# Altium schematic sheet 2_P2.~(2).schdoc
size A3; Symbol: Sheet-Symbol_A4; Device: Sheet-Symbol_A4; Company: 嘉立创EDA; Version: V1.0; Page Size: A4; @Project Name: 基于STM32的四旋翼无人机控制系统设计; @Page Count: 2; @Update Date: 2025-06-02; @Create Date: 2025-04-05; @Schematic Name: 基于STM32的无人机控制系统设计_AK09915; @Page No: 2; @Page Name: P2; @Board Name: 基于STM32的无人机控制系统设计_AK09915; @Create Time: 23:31:03; @Update Time: 17:55:10; Width: 1170; Height: 825; Region Start: 1; X Region Count: 6; Y Region Count: 4; Blade Width: 10; Title Block Position: 3
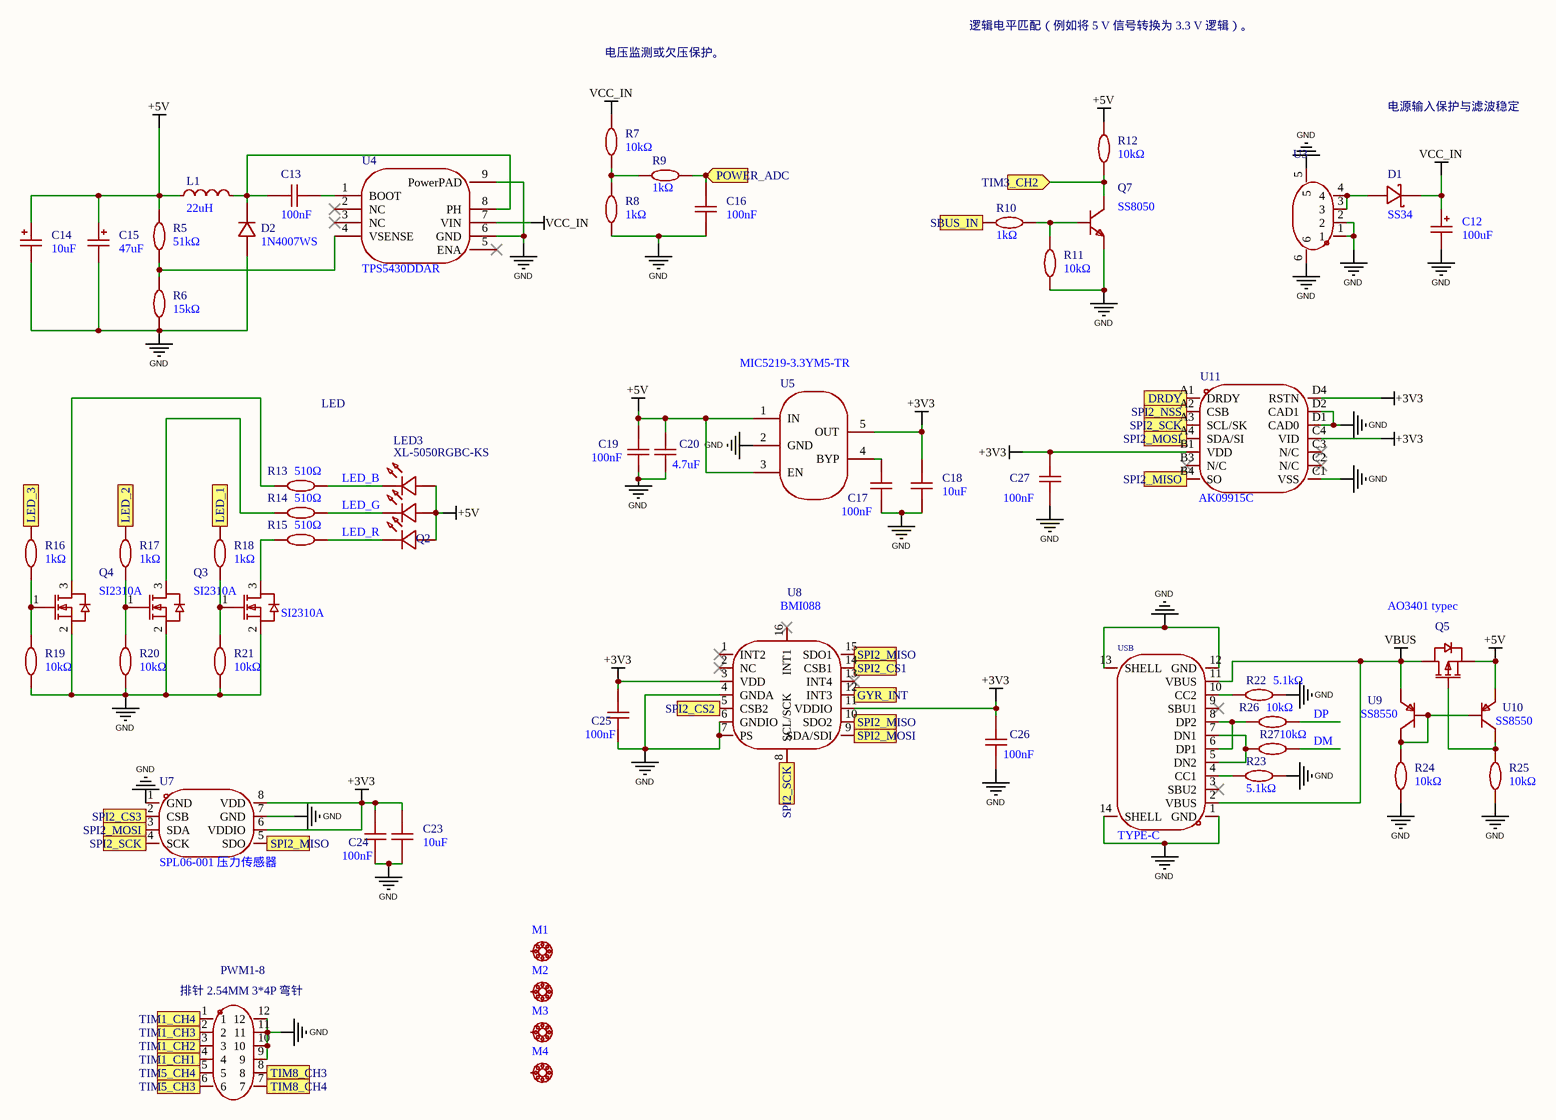
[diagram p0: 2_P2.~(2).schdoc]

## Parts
C12  100uF  [CAP-SMD_L6.0-W3.2-R-RD]
C13  100nF  [C0603]
C14  10uF  [CAP-SMD_L3.2-W1.6-RD-C7171]
C15  47uF  [CASE-A_3216]
C16  100nF  [C0603]
C17  100nF  [C0603]
C18  10uF  [C0603]
C19  100nF  [C0603]
C20  4.7uF  [C0603]
C23  10uF  [C0603]
C24  100nF  [C0603]
C25  100nF  [C0603]
C26  100nF  [C0603]
C27  100nF  [C0603]
D1  SS34  [SMA_L4.3-W2.6-LS5.2-RD]
D2  1N4007WS  [SOD-323_L1.8-W1.3-LS2.5-RD]
L1  22uH  [IND-SMD_L7.3-W6.6_MHCI06030]
LED3  XL-5050RGBC-KS  [LED-ARRAY-SMD_6P-L5.0-W5.0-TL-RD]
M1  M3螺丝  [m3_bd6.2]  (value not drawn)
M2  M3螺丝  [m3_bd6.2]  (value not drawn)
M3  M3螺丝  [m3_bd6.2]  (value not drawn)
M4  M3螺丝  [m3_bd6.2]  (value not drawn)
PWM1-8  排针 2.54MM 3*4P 弯针  [HDR-TH_12P-P2.54-H-M-R3-C4-S2.54-N]
Q2  SI2310A  [SOT-23-3_L2.9-W1.3-P0.95-LS2.4-BR]
Q3  SI2310A  [SOT-23-3_L2.9-W1.3-P0.95-LS2.4-BR]
Q4  SI2310A  [SOT-23-3_L2.9-W1.3-P0.95-LS2.4-BR]
Q5  AO3401 typec  [SOT-23-3_L2.9-W1.4-P1.90-LS2.6-BR]
Q7  SS8050  [SOT-23-3_L2.9-W1.3-P1.90-LS2.4-BR]
R5  51kΩ  [R0603]
R6  15kΩ  [R0603]
R7  10kΩ  [R0603]
R8  1kΩ  [R0603]
R9  1kΩ  [R0603]
R10  1kΩ  [R0603]
R11  10kΩ  [R0603]
R12  10kΩ  [R0603]
R13  510Ω  [R0603]
R14  510Ω  [R0603]
R15  510Ω  [R0603]
R16  1kΩ  [R0603]
R17  1kΩ  [R0603]
R18  1kΩ  [R0603]
R19  10kΩ  [R0603]
R20  10kΩ  [R0603]
R21  10kΩ  [R0603]
R22  5.1kΩ  [R0603]
R23  5.1kΩ  [R0603]
R24  10kΩ  [R0603]
R25  10kΩ  [R0603]
R26  10kΩ  [R0603]
R27  10kΩ  [R0603]
U3  ZX-SH1.0-4PWT  [CONN-SMD_4P-P1.00_MEGASTAR_ZX-SH1.0-4PWT]  (value not drawn)
U4  TPS5430DDAR  [ESOP-8_L4.9-W3.9-P1.27-LS6.0-TL-EP]
U5  MIC5219-3.3YM5-TR  [SOT-23-5_L3.0-W1.7-P0.95-LS2.8-TL]
U7  SPL06-001 压力传感器  [SENSOR-SMD_SPL06-001]
U8  BMI088  [LGA-16_L4.5-W3.0-P0.50-BL]
U9  SS8550  [SOT-23-3_L2.9-W1.3-P1.90-LS2.4-BR]
U10  SS8550  [SOT-23-3_L2.9-W1.3-P1.90-LS2.4-BR]
U11  AK09915C  [BGA-14_L1.6-W1.6-BR-AK09915C]
USB  TYPE-C  [USB-C-SMD_TYPE-C-6PIN-2MD-073]

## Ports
DRDY (in), GYR_INT (in), LED_1 (in), LED_2 (in), LED_3 (in), POWER_ADC (in), SBUS_IN (in), SPI2_CS1 (in), SPI2_CS2 (in), SPI2_CS3 (in), SPI2_MISO (in), SPI2_MOSI (in), SPI2_NSS (in), SPI2_SCK (in), TIM1_CH1 (in), TIM1_CH2 (in), TIM1_CH3 (in), TIM1_CH4 (in), TIM3_CH2 (in), TIM5_CH3 (in), TIM5_CH4 (in), TIM8_CH3 (in), TIM8_CH4 (in)

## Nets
+3V3: C18.2 C23.2 C24.1 C25.1 C26.1 C27.1 U5.5(OUT) U7.6(VDDIO) U7.8(VDD) U8.3(VDD) U8.11(VDDIO) U11.B1(VDD) U11.C4(VID) U11.D4(RSTN)
+5V: C14.1 C15.1 C19.1 C20.2 L1.1 LED3.4 LED3.5 LED3.6 Q5.2(S) R5.2 R12.1 U5.1(IN) U5.3(EN) U10.2(E)
GND: C12.2 C14.2 C15.2 C16.2 C17.2 C18.1 C19.2 C20.1 C23.1 C24.2 C25.2 C26.2 C27.2 D2.2(A) PWM1-8.9 PWM1-8.10 PWM1-8.11 PWM1-8.12 Q2.2(S) Q3.2(S) Q4.2(S) Q7.2(E) R6.1 R8.1 R11.2 R19.1 R20.1 R21.1 R22.2 R23.2 R24.1 R25.1 U3.1 U3.2 U3.5 U3.6 U4.6(GND) U4.9(PowerPAD) U5.2(GND) U7.1(GND) U7.7(GND) U8.4(GNDA) U8.6(GNDIO) U8.7(PS) U11.C1(VSS) U11.D1(CAD0) U11.D2(CAD1) USB.1(GND) USB.12(GND) USB.13(SHELL) USB.14(SHELL)
VBUS: Q5.3(D) U9.2(E) USB.2(VBUS) USB.11(VBUS)
VCC_IN: C12.1 D1.1(K) R7.2 U4.7(VIN)
DM: R27.2
DP: R26.2
DRDY: U11.A1(DRDY) ; port DRDY
GYR_INT: U8.12(INT3) ; port GYR_INT
LED_1: R18.1 ; port LED_1
LED_2: R17.1 ; port LED_2
LED_3: R16.1 ; port LED_3
LED_B: LED3.1 R13.2
LED_G: LED3.2 R14.2
LED_R: LED3.3 R15.2
POWER_ADC: C16.1 R9.1 ; port POWER_ADC
SBUS_IN: R10.2 ; port SBUS_IN
SPI2_CS1: U8.14(CSB1) ; port SPI2_CS1
SPI2_CS2: U8.5(CSB2) ; port SPI2_CS2
SPI2_CS3: U7.2(CSB) ; port SPI2_CS3
SPI2_MISO: U7.5(SDO) U8.10(SDO2) U8.15(SDO1) U11.B4(SO) ; port SPI2_MISO
SPI2_MOSI: U7.3(SDA) U8.9(SDA/SDI) U11.A4(SDA/SI) ; port SPI2_MOSI
SPI2_NSS: U11.A2(CSB) ; port SPI2_NSS
SPI2_SCK: U7.4(SCK) U8.8(SCL/SCK) U11.A3(SCL/SK) ; port SPI2_SCK
TIM1_CH1: PWM1-8.4 ; port TIM1_CH1
TIM1_CH2: PWM1-8.3 ; port TIM1_CH2
TIM1_CH3: PWM1-8.2 ; port TIM1_CH3
TIM1_CH4: PWM1-8.1 ; port TIM1_CH4
TIM3_CH2: Q7.3(C) R12.2 ; port TIM3_CH2
TIM5_CH3: PWM1-8.6 ; port TIM5_CH3
TIM5_CH4: PWM1-8.5 ; port TIM5_CH4
TIM8_CH3: PWM1-8.8 ; port TIM8_CH3
TIM8_CH4: PWM1-8.7 ; port TIM8_CH4
NetC13_1: C13.1 U4.1(BOOT)
NetC13_2: C13.2 D2.1(K) L1.2 U4.8(PH)
NetC17_1: C17.1 U5.4(BYP)
NetD1_2: D1.2(A) U3.3 U3.4
NetQ2_1: Q2.1(G) R18.2 R21.2
NetQ2_3: Q2.3(D) R15.1
NetQ3_1: Q3.1(G) R17.2 R20.2
NetQ3_3: Q3.3(D) R14.1
NetQ4_1: Q4.1(G) R16.2 R19.2
NetQ4_3: Q4.3(D) R13.1
NetQ5_1: Q5.1(G) R25.2 U10.3(C)
NetQ7_1: Q7.1(B) R10.1 R11.1
NetR5_1: R5.1 R6.2 U4.4(VSENSE)
NetR7_1: R7.1 R8.2 R9.2
NetR22_1: R22.1 USB.10(CC2)
NetR23_1: R23.1 USB.4(CC1)
NetR24_2: R24.2 U9.1(B) U9.3(C) U10.1(B)
NetR26_1: R26.1 USB.6(DP1) USB.8(DP2)
NetR27_1: R27.1 USB.5(DN2) USB.7(DN1)

Not connected (* = marked no-connect by the designer): M1 1; M2 1; M3 1; M4 1; U4 2(NC)* 3(NC)* 5(ENA)*; U8 1(INT2)* 2(NC)* 13(INT4)* 16(INT1)*; U11 B3(N/C)* C2(N/C)* C3(N/C)*; USB 3(SBU2)* 9(SBU1)*

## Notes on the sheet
- 电压监测或欠压保护。
- 逻辑电平匹配（例如将 5 V 信号转换为 3.3 V 逻辑）。
- 电源输入保护与滤波稳定
- LED

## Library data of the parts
C12 = TAJC107K016RNJ: Manufacturer: Kyocera AVX; Symbol: TAJC107K016RNJ_C11375; Add into BOM: yes; Tolerance: ±10%; Rated Voltage: 16V; Equivalent Series Resistance(ESR): 1Ω@100kHz
C13 C16 C17 C19 C24-C27 = CC0603KRX7R9BB104: Manufacturer: YAGEO(国巨); Add into BOM: yes; Tolerance: ±10%; Voltage Rated: 50V; Temperature Coefficient: X7R
C14 = TAJA106K016RNJ: Manufacturer: Kyocera AVX; Add into BOM: yes; Tolerance: ±10%; Rated Voltage: 16V; Equivalent Series Resistance(ESR): 3Ω@100kHz
C15 = TAJA476K006RNJ: Manufacturer: Kyocera AVX; Add into BOM: yes; Tolerance: ±10%; Rated Voltage: 6.3V; Equivalent Series Resistance(ESR): 1.6Ω@100kHz
C18 C23 = CL10A106MA8NRNC: Manufacturer: SAMSUNG(三星); Add into BOM: yes; Tolerance: ±20%; Voltage Rated: 25V; Temperature Coefficient: X5R
C20 = CL10A475KO8NNNC: Manufacturer: SAMSUNG(三星); Add into BOM: yes; Tolerance: ±10%; Voltage Rated: 16V; Temperature Coefficient: X5R
D1 = SS34_C8678: Manufacturer: MDD(辰达半导体); Add into BOM: yes; Diode Configuration: 独立式; Forward Voltage (Vf@If): 550mV@3A; Reverse Voltage (Vr): 40V; Rectified Current: 3A; Reverse Leakage Current (Ir): 500uA@40V
D2 = 1N4007WS: Manufacturer: MDD(辰达半导体); Add into BOM: yes; Diode Configuration: 独立式; Forward Voltage (Vf@If): 1.1V@1A; Reverse Voltage (Vr): 1kV; Rectified Current: 1A; Reverse Leakage Current: 5uA@1kV
L1 = SMMS0630-220M: Manufacturer: SXN(顺翔诺); Add into BOM: yes; Tolerance: ±20%; Saturation Current (Isat): 3.5A; DC Resistance (DCR): 135mΩ; Type: 一体成型电感
LED3 = XL-5050RGBC-KS: Manufacturer: XINGLIGHT(成兴光); Add into BOM: yes
M1-M4 = M3螺丝: Add into BOM: yes
PWM1-8 = 排针 2.54MM 3*4P 弯针: Manufacturer: null; Add into BOM: yes
Q2-Q4 = SI2310A: Manufacturer: UMW(友台半导体); Add into BOM: yes; Type: 1个N沟道; Drain Source Voltage (Vdss): 60V; Continuous Drain Current (Id): 3A; Power Dissipation (Pd): 1.38W; Drain Source On Resistance (RDS(on)@Vgs,Id): 90mΩ@10V,3A; Gate Threshold Voltage (Vgs(th)@Id): 3V@250uA
Q5 = AO3401_C727156: Manufacturer: TWGMC(台湾迪嘉); Add into BOM: yes; Type: 1个P沟道; Drain Source Voltage (Vdss): 30V; Continuous Drain Current (Id): 4.2A; Power Dissipation (Pd): 350mW; Drain Source On Resistance (RDS(on)@Vgs,Id): 65mΩ@10V,4.2A; Gate Threshold Voltage (Vgs(th)@Id): 1.3V@250uA
Q7 = SS8050_C7420370: Manufacturer: 宏迦橙; Add into BOM: yes; Transistor Type: NPN; Collector Current (Ic): 1.5A; Collector-Emitter Breakdown Voltage (Vceo): 25V; Power Dissipation (Pd): 300mW; DC Current Gain (hFE@Ic,Vce): 120@100mA,1.0V; Transition Frequency (fT): 100MHz; Collector Cut-Off Current (Icbo): 100nA; Collector-Emitter Saturation Voltage (VCE(sat)@Ic,Ib): 500mV@800mA,80mA
R5 = 0603WAF5102T5E: Manufacturer: UNI-ROYAL(厚声); Add into BOM: yes; Tolerance: ±1%; Power(Watts): 100mW; Overload Voltage (Max): 75V; Temperature Coefficient: ±100ppm/℃
R6 = 0603WAF1502T5E: Manufacturer: UNI-ROYAL(厚声); Add into BOM: yes; Tolerance: ±1%; Power(Watts): 100mW; Overload Voltage (Max): 75V; Temperature Coefficient: ±100ppm/℃
R7 R11 R12 R19-R21 R24-R27 = 0603WAF1002T5E: Manufacturer: UNI-ROYAL(厚声); Add into BOM: yes; Tolerance: ±1%; Power(Watts): 100mW; Overload Voltage (Max): 75V; Temperature Coefficient: ±100ppm/℃
R8-R10 R16-R18 = 0603WAF1001T5E: Manufacturer: UNI-ROYAL(厚声); Add into BOM: yes; Tolerance: ±1%; Power(Watts): 100mW; Overload Voltage (Max): 75V; Temperature Coefficient: ±100ppm/℃
R13-R15 = 0603WAF5100T5E: Manufacturer: UNI-ROYAL(厚声); Add into BOM: yes; Tolerance: ±1%; Power(Watts): 100mW; Overload Voltage (Max): 75V; Temperature Coefficient: ±100ppm/℃
R22 R23 = 0603WAF5101T5E: Manufacturer: UNI-ROYAL(厚声); Add into BOM: yes; Tolerance: ±1%; Power(Watts): 100mW; Overload Voltage (Max): 75V; Temperature Coefficient: ±100ppm/℃
U3 = ZX-SH1.0-4PWT: Manufacturer: Megastar(兆星); Add into BOM: yes; Pins Structure: 1x4P; Pitch: 1mm; Reference Series: SH; Number of PINs Per Row: 4; Current Rating (Max): 1A
U4 = TPS5430DDAR: Manufacturer: TI(德州仪器); Add into BOM: yes; Function: 降压型; Output Type: 可调; Input Voltage: 5.5V~36V; Output Voltage: 1.221V~32.04V; Output Current (Max): 3A; Switching Frequency: 500kHz; Synchronous Rectification: 否; Number of Outputs: 1; Topology: 降压式; Switch tube (built-in/external): 内置
U5 = MIC5219-3.3YM5-TR: Manufacturer: MICROCHIP(美国微芯); Add into BOM: yes; Output Type: 固定; Maximum Input Voltage: 12V; Output Voltage: 3.3V; MAX Output Current: 500mA; Power Supply Rejection Ratio (PSRR): 75dB@(120Hz); Dropout Voltage: 600mV@(500mA); standby current: 8uA; Output Polarity: 正极; Number of Outputs: 1
U7 = SPL06-001_C2684428: Manufacturer: Goertek(歌尔); Add into BOM: yes
U8 = BMI088: Manufacturer: Bosch(博世); Add into BOM: yes; Sensor Type: 加速度计陀螺仪
U9 U10 = SS8550_C7420371: Manufacturer: 宏迦橙; Add into BOM: yes; Transistor Type: PNP; Collector Current (Ic): 1.5A; Collector-Emitter Breakdown Voltage (Vceo): 25V; Power Dissipation (Pd): 300mW; DC Current Gain (hFE@Ic,Vce): 120@100mA,1.0V; Transition Frequency (fT): 100MHz; Collector Cut-Off Current (Icbo): 100nA; Collector-Emitter Saturation Voltage (VCE(sat)@Ic,Ib): 500mV@800mA,80mA
U11 = AK09915C: Manufacturer: AKM; Add into BOM: yes
USB = TYPE-C 16PIN 2MD(073): Manufacturer: SHOU HAN(首韩); Add into BOM: yes; Gender: 母座; Number of Contacts: 16; Number of Ports: 1; Current Rating - Power (Max): 5A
